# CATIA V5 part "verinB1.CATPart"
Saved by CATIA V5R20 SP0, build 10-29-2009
Part number: verinB1
Bounding box of the stored display mesh (mm): x -35 to 35, y -180 to 16.076, z 197.703 to 738.241
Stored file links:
  D:\Dropbox\Pack 1 sylvain\mmoreau\mmoreau\mmoreau\fin\verinB1.CATPart
  U:\think motion\fin\think motion2.CATProduct
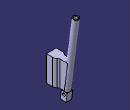
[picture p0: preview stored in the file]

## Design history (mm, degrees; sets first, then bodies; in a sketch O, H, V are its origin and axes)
Set1
  Point1: linked copy from another document
  Line1: linked copy from another document
  Point2: linked copy from another document
  Point3: linked copy from another document
Body1 (main body)
  Sketch1 on yz-plane, origin (0, 0, 0), H (0, 1, 0), V (0, 0, 1)
    line L1 (-23.5682, 738.241) -> (-95.1241, 203.003)
    point P1 (-23.5682, 738.241)
    point P2 (-95.1241, 203.003)
    reference projected line E1 (-3.1227, 740.2423) -> (-69.3781, 244.6515) from Line1
    reference projected line E2 (-3.1227, 740.2423) -> (-69.3781, 244.6515) from Line1
    line L2 (-95.1241, 203.003) -> (-75.3004, 200.3527)
    point P3 (-95.1241, 203.003)
    point P4 (-75.3004, 200.3527)
    reference projected line E3 (-3.1227, 740.2423) -> (-69.3781, 244.6515) from Line1
    line L3 (-23.5682, 738.241) -> (-3.7445, 735.5908)
    point P5 (-23.5682, 738.241)
    point P6 (-3.7445, 735.5908)
    reference projected line E4 (-3.1227, 740.2423) -> (-69.3781, 244.6515) from Line1
    reference projected point E5 (-70, 240) from Point2
    reference projected point E6 (-3.7445, 735.5908) from Point1
    distance E2 L1 = 20
    distance L2 E5 = 40
    parallelism: E1 L1, L3 L2
    perpendicularity: L2 L1
    coincidence: E3 P4, P3 P2, E4 P6, P1 P5, E6 L3
  Shaft1: profile Sketch1, axis Line1, angle 360
  Sketch2 on yz-plane, origin (0, 0, 0), H (0, 1, 0), V (0, 0, 1)
    circle A1 centre (-70, 240) radius 10
    point P1 (-70, 240)
    reference projected point E1 (-70, 240) from Point2
    radius A1 = 10
    coincidence: E1 P1
  Pocket1: profile Sketch2, direction (-1, 0, 0), length 20, mirrored extent
  Sketch3 on face of Shaft1 from Sketch1.L3, origin (0, 96.6387, 722.1706), H (-1, 0, 0), V (0, -0.9912, 0.1325)
    circle A1 centre (0, 101.0534) radius 15
    point P1 (0, 101.0534)
    radius A1 = 15
    coincidence: P1 V
  Pocket2: profile Sketch3, direction (0, -0.1325, -0.9912), length 450
  Sketch4 on xy-plane, origin (0, 0, 0), H (1, 0, 0), V (0, 1, 0)
    line L1 (20, 0) -> (20, -98)
    point P1 (20, 0)
    construction line L2 (40, -118) -> (35, -118)
    point P2 (35, -118)
    line L3 (35, -135.7492) -> (35, -180)
    point P3 (35, -180)
    arc A1 centre (40, -98) radius 20 from (25.4545, -111.727) to (20, -98) cw
    point P4 (40, -118)
    point P5 (20, -98)
    arc A2 centre (0, -135.7492) radius 35 from (25.4545, -111.727) to (35, -135.7492) cw
    point P7 (25.4545, -111.727)
    point P8 (35, -135.7492)
    point P10 (-35, -180)
    point P11 (-35, -135.7492)
    line L4 (-35, -135.7492) -> (-35, -180)
    point P12 (-25.4545, -111.727)
    arc A3 centre (0, -135.7492) radius 35 from (-25.4545, -111.727) to (-35, -135.7492) ccw
    point P14 (-20, -98)
    arc A4 centre (-40, -98) radius 20 from (-25.4545, -111.727) to (-20, -98) ccw
    point P16 (-20, 0)
    line L5 (-20, 0) -> (-20, -98)
    line L6 (20, 0) -> (-20, 0)
    line L7 (35, -180) -> (-35, -180)
    point P17 (35, -180)
    point P18 (-35, -180)
    distance L1 V = 20
    distance L3 V = 35
    distance L2 H = 118
    radius A1 = 20
    radius A2 = 35
    distance L7 L6 = 180
    vertical: L1 V, L3 V
    horizontal: L2 H, L6 H, L7 H
    coincidence: P1 H, A1 P4, L3 P2, P17 L3, P18 L4, P3 L7, P3 P17, P10 P18
    tangency: A1 L2, A1 L1, A2 L3, A2 A1
    symmetry: P3 P10 V, P8 P11 V, L3 L4 V, P7 P12 V, A2 A3 V, P5 P14 V, A1 A4 V, P1 P16 V, L1 L5 V
  Pad1: profile Sketch4, direction (0, 0, 1), length 445, opposite side length -264
  Sketch5 on face of Shaft1 from Sketch1.L3, origin (0, 96.5485, 722.1826), H (-1, 0, 0), V (0, -0.9912, 0.1325)
    circle A1 centre (0, 101.1853) radius 15
    point P1 (0, 101.1853)
    reference projected point E1 (0, 101.1853) from Point3
    arc A2 centre (0, 101.1853) radius 20 from (-20, 101.1853) to (20, 101.1853) ccw
    point P2 (0, 101.1853)
    reference projected point E2 (0, 101.1853) from Point3
    line L1 (-20, 101.1853) -> (-20, 25.1853)
    point P3 (-20, 101.1853)
    point P4 (-20, 25.1853)
    reference projected point E3 (0, 101.1853) from Point3
    point P5 (20, 25.1853)
    point P6 (20, 101.1853)
    line L2 (20, 101.1853) -> (20, 25.1853)
    line L3 (-20, 25.1853) -> (20, 25.1853)
    point P7 (-20, 101.1853)
    point P8 (20, 101.1853)
    radius A1 = 15
    radius A2 = 20
    distance P4 E3 V = 76
    coincidence: P1 E1, P2 E2, P3 A2, L2 P8, L1 P7, P3 P7, P6 P8
    vertical: L1 V
    tangency: L1 A2
    symmetry: P4 P5 V, P3 P6 V, L1 L2 V
    horizontal: L3 H
  Pocket3: profile Sketch5, direction (0, -0.1325, -0.9912), length 490
  Sketch6 on yz-plane, origin (0, 0, 0), H (0, 1, 0), V (0, 0, 1)
    line L1 (-87.1734, 262.4738) -> (-95.1241, 203.003)
    line L2 (-95.1241, 203.003) -> (-55.4768, 197.7025)
    line L3 (-55.4768, 197.7025) -> (-47.5262, 257.1734)
    line L4 (-47.5262, 257.1734) -> (-87.1734, 262.4738)
    reference projected line E1 (-3.7445, 735.5908) -> (-70, 240) from Line1
    reference projected line E2 through (-100.293, 13.4082) direction (-0.1325, -0.9912) from axis of face of Pocket3
    reference projected line E3 (-55.4768, 197.7025) -> (-95.1241, 203.003) from edge [face of Shaft1 from Sketch1.L1 | face of Shaft1 from Sketch1.L2]
    reference projected point E4 (-70, 240) from Point2
    circle A1 centre (-70, 240) radius 10
    point P5 (-70, 240)
    reference projected point E5 (-70, 240) from Point2
    reference projected circle E6 centre (-70, 240) radius 10 from edge [face of Pocket3 | face of Pocket1 from Sketch2.A1]
    distance L1 L3 = 40
    distance L4 E4 = 20
    parallelism: L4 L2, E1 L1
    perpendicularity: L1 L2
    symmetry: L1 L3 E2
    coincidence: L2 E3, P5 E5, E6 A1
  Pad2: profile Sketch6, direction (1, 0, 0), length 20, mirrored extent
